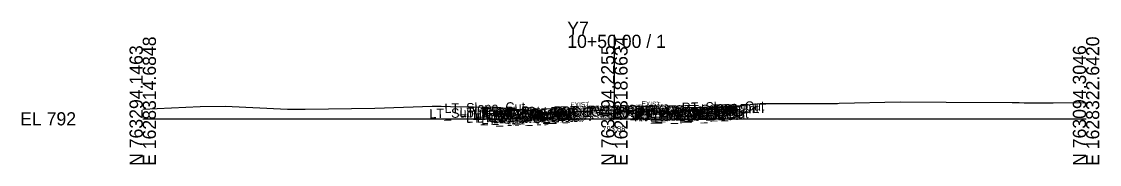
# Model space of a CAD drawing. Extents: x -26 to 203, y -10 to 3017.
# Drawn here: x -25.7 to 202.8, y 990.3 to 1020.7 of the extents above; entities that cross this region are included whole.
import ezdxf

# ---------------------------------------------------------------- set-up
doc = ezdxf.new("R2010")
doc.units = 0
for name, color, linetype in [('Default', 7, 'Continuous'), ('Exist Cross Section Cell', 7, 'Continuous'), ('Exist XS Center Line Elevation Label', 7, 'Continuous'), ('Exist XS Ground Line', 7, 'Continuous'), ('Prop CMT Pvmt Course 1', 7, 'Continuous'), ('Prop XS SE Text', 7, 'Continuous'), ('Scratch_Level_0', 7, 'Continuous')]:
    doc.layers.add(name, color=color, linetype=linetype)

msp = doc.modelspace()

# ---------------------------------------------------------------- linework, layer by layer
at = {"layer": 'Exist Cross Section Cell'}
for p, q in [((100, 1000), (100, 1017.85)), ((0, 1000), (100, 1000)), ((100, 1000), (200, 1000))]:
    msp.add_line(p, q, dxfattribs=at)
at = {"layer": 'Exist XS Ground Line'}
msp.add_lwpolyline([(0, 1002.05), (12.19, 1002.61), (17.45, 1002.71), (30.69, 1002.04), (34.41, 1002.05), (49.19, 1002.26), (61.34, 1002.69), (63.3, 1002.68), (65.26, 1002.61), (75.06, 1002.44), (83.91, 1001.58), (84.57, 1001.53), (85.03, 1001.22), (85.69, 1001.25), (99.53, 1001.89), (100, 1001.88), (114.21, 1001.49), (114.96, 1001.47), (115.51, 1001.74), (116.72, 1001.84), (130.93, 1003.25), (146.57, 1003.26), (147.31, 1003.25), (147.67, 1003.3), (160.57, 1003.62), (170.31, 1003.56), (184.37, 1003.45), (185.8, 1003.46), (186.87, 1003.42), (193.05, 1003.4), (200, 1003.44)], dxfattribs=at)
at = {"layer": 'Prop CMT Pvmt Course 1'}
for points in [[(100, 1001.63), (100, 1001.88)], [(100, 1001.63), (100, 1001.88)], [(100, 1001.75), (100, 1001.63), (100, 1001.63)], [(100, 1001.75), (100, 1001.63), (100, 1001.63)]]:
    msp.add_lwpolyline(points, dxfattribs=at)

# ---------------------------------------------------------------- texts
at = {"layer": 'Default'}
msp.add_text('-', height=0.0001, dxfattribs=at).set_placement((0, 1000))
at = {"layer": 'Exist Cross Section Cell'}
for s, p in [('Y7', (90, 1017.85)), ('10+50.00 / 1', (90, 1015.05)), ('EL 792', (-26, 998.6))]:
    msp.add_text(s, height=2.8, dxfattribs=at).set_placement(p)
for s, p in [('E 1628314.6848', (2.8, 990)), ('E 1628318.6634', (102.8, 990)), ('E 1628322.6420', (202.8, 990)), ('N 763294.1463', (0, 990)), ('N 763194.2255', (100, 990)), ('N 763094.3046', (200, 990))]:
    msp.add_text(s, height=2.8, rotation=90, dxfattribs=at).set_placement(p)
at = {"layer": 'Exist XS Center Line Elevation Label'}
msp.add_text('793.88', height=1.2, dxfattribs=at).set_placement((97.43, 997.28))
at = {"layer": 'Prop XS SE Text'}
for rotation, p in [(2.8624, (90.7, 1002.42)), (358.2816, (105.74, 1002.71))]:
    msp.add_text('EXIST.', height=1, rotation=rotation, dxfattribs=at).set_placement(p)
at = {"layer": 'Scratch_Level_0'}
for s, p in [('LT_Slope_Cut', (63.99, 1001.24)), ('RT_Slope_Cut', (114.29, 1001.42)), ('LT_Sub_Trench_Out_DLT', (60.79, 1000.11)), ('LT_CSLP_Pnt', (67.19, 1000.36)), ('LT_CG1_Shelf_Out', (68.57, 999.13)), ('LT_PV_Sub_Tie_Out', (70.01, 999.92)), ('LT_CG_Top_Face', (70.28, 1000.2)), ('LT_CG_Top_BOC', (70.8, 1000.22)), ('LT_CG_Bot_BOC', (70.84, 999.19)), ('LT_CG_Top_Gut', (71.26, 999.71)), ('LT_Sub_OEOP', (71.78, 998.85)), ('LT_PV_OEEOP_EG', (72.6, 999.97)), ('LT_Sub_OEEOP', (74.27, 999)), ('LT_PV2_OEEOP', (74.36, 999.67)), ('LT_PV3_OEEOP', (74.36, 999.33)), ('LT_PV1_OEEOP', (74.93, 999.8)), ('LT_CG_Bot_IE', (74.94, 999.35)), ('LT_Sub_OEOT', (75.1, 999.02)), ('LT_PV2_OEOT', (75.2, 999.68)), ('LT_PV3_OEOT', (75.2, 999.35)), ('LT_PV1_OEOT', (75.76, 999.95)), ('RT_PV_IEEOP_EG', (88.16, 1000.64)), ('LT_PV_IEEOP_EG', (88.21, 1000.64)), ('RT_PV2_IEEOP', (89.93, 1000.43)), ('RT_PV3_IEEOP', (89.93, 1000.1)), ('LT_PV2_IEEOP', (89.97, 1000.43)), ('LT_PV3_IEEOP', (89.97, 1000.1)), ('RT_PV1_IEEOP', (90.49, 1000.56)), ('LT_PV1_IEEOP', (90.54, 1000.57)), ('PV2_PGL', (93.93, 1000.51)), ('PV1_PGL', (94.49, 1000.77)), ('RT_PV_Sub_Tie_Out', (99.87, 1000.17)), ('RT_Sub_Trench_Out_DLT', (100.29, 1000.62)), ('RT_PV_OEEOP_EG', (102.48, 1000.22)), ('RT_Sub_OEEOP', (104.15, 999.45)), ('RT_CG_Top_Face', (104.24, 1000.7)), ('RT_PV2_OEEOP', (104.24, 1000.12)), ('RT_PV3_OEEOP', (104.24, 999.78)), ('RT_CG1_Shelf_Out', (104.53, 999.67)), ('RT_PV1_OEEOP', (104.81, 1000.25)), ('RT_CG_Bot_IE', (104.89, 999.79)), ('RT_Sub_OEOT', (105.05, 999.46)), ('RT_PV2_OEOT', (105.15, 1000.13)), ('RT_PV3_OEOT', (105.15, 999.8)), ('RT_CG_Top_Gut', (105.21, 1000.22)), ('RT_PV1_OEOT', (105.71, 1000.39)), ('RT_CG_Top_BOC', (105.76, 1000.72)), ('RT_CG_Bot_BOC', (105.79, 999.71)), ('RT_Sub_OEOP', (108.43, 999.4)), ('RT_CSLP_Pnt', (113.15, 1000.87))]:
    msp.add_text(s, height=2, rotation=1.1458, dxfattribs=at).set_placement(p)

doc.saveas('drawing.dxf')
